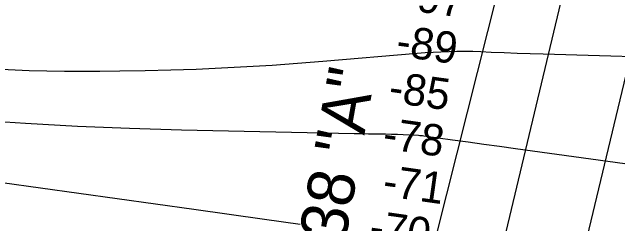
# Model space of a CAD drawing. Extents: x 3508733 to 3546731, y 546897 to 572481.
# Drawn here: x 3524852 to 3526144, y 564701 to 565153 of the extents above; entities that cross this region are included whole.
import ezdxf

# ---------------------------------------------------------------- set-up
doc = ezdxf.new("R2010")
doc.units = 0
for name, color, linetype in [('V-CHAN-NAID', 7, 'Continuous'), ('V-RIVR-RANG', 7, 'Continuous'), ('V-TOPO-MINR', 7, 'Continuous'), ('V-UTIL-LINE', 7, 'Continuous')]:
    doc.layers.add(name, color=color, linetype=linetype)

msp = doc.modelspace()

# ---------------------------------------------------------------- linework, layer by layer
at = {"layer": 'V-TOPO-MINR'}
for points in [[(3524812.3, 565031.6), (3524887.7, 565028.5), (3524963.3, 565027.1), (3525038.8, 565026.9), (3525081.5, 565027.3), (3525135.7, 565028.2), (3525189.9, 565029.4), (3525244.1, 565031.3), (3525298.3, 565033.7), (3525352.5, 565036.6), (3525406.6, 565040), (3525460.7, 565043.9), (3525514.8, 565048.2), (3525715.7, 565065.2), (3525732.6, 565066.5), (3525749.6, 565067.7), (3525766.6, 565068.5), (3525783.7, 565069.2), (3525800.7, 565069.6), (3525817.7, 565069.7), (3525834.7, 565069.4), (3525851.7, 565068.8), (3525873.3, 565067.8), (3525901.1, 565066.6), (3525928.9, 565065.5), (3525956.7, 565064.6), (3525984.6, 565063.7), (3526320.7, 565053.9)], [(3524063.3, 564925.1), (3524157.2, 564905.6), (3524251.2, 564886.5), (3524345.3, 564867.8), (3524483.3, 564840.7), (3524508.5, 564836), (3524533.7, 564831.5), (3524559, 564827.5), (3524584.3, 564823.7), (3525239.3, 564732.3), (3525314.8, 564721.8), (3525390.3, 564711.2), (3525465.9, 564700.6)], [(3524769.3, 564923.3), (3524880.2, 564915.9), (3524991.1, 564909.6), (3525102.1, 564905.1), (3525213.2, 564901.9), (3525581.4, 564893.9), (3525596.8, 564893.6), (3525612.1, 564893.3), (3525627.5, 564893.1), (3525642.9, 564892.9), (3525648.3, 564892.8), (3525661, 564892.6), (3525673.6, 564892.2), (3525686.2, 564891.7), (3525698.8, 564891.1), (3525718.4, 564890), (3525721.2, 564889.8), (3525724, 564889.6), (3525726.9, 564889.3), (3525729.7, 564888.9), (3525791.1, 564880.5), (3525824.7, 564875.9), (3525858.2, 564871.3), (3525891.7, 564866.7), (3525925.3, 564862.1), (3526889.7, 564729.3)]]:
    msp.add_lwpolyline(points, dxfattribs=at)
at = {"layer": 'V-UTIL-LINE'}
for points in [[(3525407, 563288.4), (3526063.3, 565894.4)], [(3526187.4, 565867.5), (3525566.5, 563265.6)], [(3525736, 563241.3), (3526363.9, 565863)]]:
    msp.add_lwpolyline(points, dxfattribs=at)

# ---------------------------------------------------------------- texts
at = {"layer": 'V-CHAN-NAID'}
msp.add_text('MILE 138 "A"', height=100, rotation=79.8167, dxfattribs=at).set_placement((3525486.8, 564242.5))
at = {"layer": 'V-RIVR-RANG'}
for s, p in [('-97', (3525683.3, 565158.8)), ('-89', (3525668.6, 565059.9)), ('-85', (3525652.6, 564961.2)), ('-78', (3525640, 564862)), ('-71', (3525640.1, 564761)), ('-70', (3525611.3, 564664))]:
    msp.add_text(s, height=67, rotation=351.9879, dxfattribs=at).set_placement(p)

doc.saveas('drawing.dxf')
